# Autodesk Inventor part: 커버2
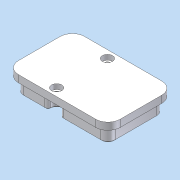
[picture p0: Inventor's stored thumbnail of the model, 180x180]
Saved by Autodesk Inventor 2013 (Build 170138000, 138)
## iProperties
Company: 한국ATC센터
Created: 2015-04
Part Number: 커버2
Document SubType Name: Modeling
Designer: KYOUNG IL JANG
Density: 1 g/cm^3
Material: 일반
Mass: 82.2849 g
Surface Area: 213.51 cm^2
Volume: 82.2849 cm^3
Author: KYOUNG IL JANG
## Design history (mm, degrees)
node "작업 평면1"
sketch "스케치1"
  geometry: L1 (-16.986, 27.5)-(-38, 27.5) reference; L2 (-45, 20.5)-(-45, -20.5) reference; L3 (-38, -27.5)-(-16.986, -27.5) reference; L4 (0.986, -27.5)-(38, -27.5) reference; L5 (45, -20.5)-(45, 20.5) reference; L6 (38, 27.5)-(0.986, 27.5) reference; C1 r 25 at (15, 0); A1 r 3 centre (-16.986, 24.5) between (-13.991, 24.667) and (-16.986, 27.5) reference; A2 r 7 centre (-38, 20.5) between (-38, 27.5) and (-45, 20.5) reference; A3 r 7 centre (-38, -20.5) between (-45, -20.5) and (-38, -27.5) reference; A4 r 3 centre (-16.986, -24.5) between (-16.986, -27.5) and (-13.991, -24.667) reference; A5 r 6 centre (-8, -25) between (-2.009, -24.667) and (-13.991, -24.667) reference; A6 r 3 centre (0.986, -24.5) between (-2.009, -24.667) and (0.986, -27.5) reference; A7 r 7 centre (38, -20.5) between (38, -27.5) and (45, -20.5) reference; A8 r 7 centre (38, 20.5) between (45, 20.5) and (38, 27.5) reference; A9 r 3 centre (0.986, 24.5) between (0.986, 27.5) and (-2.009, 24.667) reference; A10 r 6 centre (-8, 25) between (-13.991, 24.667) and (-2.009, 24.667) reference; 1 further point
  constraints: 20 point on circle, 12 end point, 11 centre point, 4 horizontal, 2 vertical, 36 other
extrude "돌출1" new body sketch "스케치1" distance "d0" = 14; taper "d1" = 0 deg
sketch "스케치2"
  geometry: L1 (38, -32.5)-(-38, -32.5) reference; L2 (50, 20.5)-(50, -20.5) reference; L3 (-38, 32.5)-(38, 32.5) reference; L4 (-50, -20.5)-(-50, 20.5) reference; A1 r 12 centre (38, -20.5) between (38, -32.5) and (50, -20.5) reference; A2 r 12 centre (38, 20.5) between (50, 20.5) and (38, 32.5) reference; A3 r 12 centre (-38, 20.5) between (-38, 32.5) and (-50, 20.5) reference; A4 r 12 centre (-38, -20.5) between (-50, -20.5) and (-38, -32.5) reference; 1 further point
extrude "돌출2" join sketch "스케치2" distance "d2" = 7; taper "d3" = 0 deg
sketch "스케치3"
  geometry: C1 r 2.458 at (-8, 25) reference; C2 r 2.458 at (-8, -25) reference; 1 further point
hole "구멍1" sketch "스케치3" at (-8, -25), (-8, 25) diameter "d4" = 6; stored, may be unused: countersink angle "d8" = 90 deg, drill point angle "d10" = 118 deg; dims "d5" = 6, "d6" = 10, "d7" = 5, "d9" = 8
fillet "모깎기1" dims "d11" = 0.3
chamfer "모따기1" distance "d12" = 1; stored, may be unused: second distance "d13" = 2, angle "d14" = 45 deg
node "솔리드1"
node "참조2"
node "참조3"
node "참조4"
node "참조5"
node "참조6"
node "참조7"
node "참조8"
node "참조9"
node "참조10"
node "참조11"
